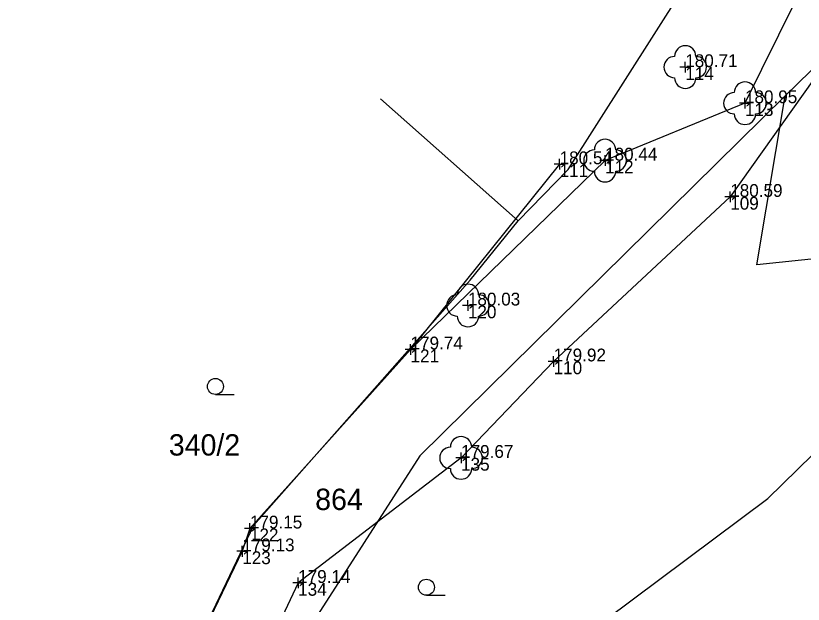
# Model space of a CAD drawing. Extents: x -744860 to -744734, y -966759 to -966608.
# Drawn here: x -744834.98 to -744798.06, y -966721.14 to -966693.56 of the extents above; entities that cross this region are included whole.
import ezdxf

# ---------------------------------------------------------------- set-up
doc = ezdxf.new("R2010")
doc.units = 0
for name, color, linetype in [('Bod polohopisu - výška', 7, 'Continuous'), ('Bod polohopisu - značka', 7, 'Continuous'), ('Bod polohopisu - číslo', 7, 'Continuous'), ('KM', 7, 'Continuous'), ('Ploty_opěrné zdi', 7, 'Continuous'), ('Stromy_porost', 7, 'Continuous'), ('Vstup na pozemek', 7, 'Continuous')]:
    doc.layers.add(name, color=color, linetype=linetype)

msp = doc.modelspace()

# ---------------------------------------------------------------- linework, layer by layer
at = {"layer": 'Bod polohopisu - značka'}
for p, q in [((-744803.59, -966695.97), (-744803.84, -966695.97)), ((-744803.59, -966695.97), (-744803.59, -966695.72)), ((-744803.59, -966695.97), (-744803.34, -966695.97)), ((-744803.59, -966695.97), (-744803.59, -966696.22)), ((-744800.79, -966697.66), (-744800.79, -966697.41)), ((-744800.79, -966697.66), (-744801.04, -966697.66)), ((-744800.79, -966697.66), (-744800.54, -966697.66)), ((-744800.79, -966697.66), (-744800.79, -966697.91)), ((-744807.35, -966700.35), (-744807.35, -966700.1)), ((-744809.48, -966700.52), (-744809.48, -966700.27)), ((-744807.35, -966700.35), (-744807.6, -966700.35)), ((-744807.35, -966700.35), (-744807.1, -966700.35)), ((-744807.35, -966700.35), (-744807.35, -966700.6)), ((-744809.48, -966700.52), (-744809.73, -966700.52)), ((-744809.48, -966700.52), (-744809.23, -966700.52)), ((-744809.48, -966700.52), (-744809.48, -966700.77)), ((-744801.48, -966702.05), (-744801.48, -966701.8)), ((-744801.48, -966702.05), (-744801.73, -966702.05)), ((-744801.48, -966702.05), (-744801.23, -966702.05)), ((-744801.48, -966702.05), (-744801.48, -966702.3)), ((-744813.78, -966707.14), (-744813.78, -966706.89)), ((-744813.78, -966707.14), (-744814.03, -966707.14)), ((-744813.78, -966707.14), (-744813.53, -966707.14)), ((-744813.78, -966707.14), (-744813.78, -966707.39)), ((-744816.47, -966709.2), (-744816.47, -966708.95)), ((-744816.47, -966709.2), (-744816.72, -966709.2)), ((-744816.47, -966709.2), (-744816.22, -966709.2)), ((-744816.47, -966709.2), (-744816.47, -966709.45)), ((-744809.76, -966709.76), (-744809.76, -966709.51)), ((-744809.76, -966709.76), (-744810.01, -966709.76)), ((-744809.76, -966709.76), (-744809.51, -966709.76)), ((-744809.76, -966709.76), (-744809.76, -966710.01)), ((-744814.1, -966714.28), (-744814.1, -966714.03)), ((-744814.1, -966714.28), (-744814.35, -966714.28)), ((-744814.1, -966714.28), (-744813.85, -966714.28)), ((-744814.1, -966714.28), (-744814.1, -966714.53)), ((-744824, -966717.59), (-744824, -966717.34)), ((-744824, -966717.59), (-744824.25, -966717.59)), ((-744824, -966717.59), (-744823.75, -966717.59)), ((-744824, -966717.59), (-744824, -966717.84)), ((-744824.36, -966718.66), (-744824.36, -966718.41)), ((-744824.36, -966718.66), (-744824.61, -966718.66)), ((-744824.36, -966718.66), (-744824.11, -966718.66)), ((-744824.36, -966718.66), (-744824.36, -966718.91)), ((-744821.74, -966720.14), (-744821.74, -966719.89)), ((-744821.74, -966720.14), (-744821.99, -966720.14)), ((-744821.74, -966720.14), (-744821.49, -966720.14)), ((-744821.74, -966720.14), (-744821.74, -966720.39))]:
    msp.add_line(p, q, dxfattribs=at)
at = {"layer": 'KM'}
for p, q in [((-744811.42, -966703.17), (-744817.88, -966697.46)), ((-744825.617, -966711.31), (-744824.742, -966711.31)), ((-744815.726, -966720.72), (-744814.851, -966720.72))]:
    msp.add_line(p, q, dxfattribs=at)
for points in [[(-744785.56, -966685.37), (-744792.95, -966691.5), (-744798.91, -966697.31)], [(-744811.42, -966703.17), (-744809.08, -966700.77), (-744801.02, -966688.1)], [(-744798.91, -966697.31), (-744816.04, -966714.19), (-744827.57, -966732.14), (-744834.06, -966749.64)], [(-744789.3, -966704.1), (-744800.23, -966705.23), (-744798.91, -966697.31)], [(-744829.77, -966729.91), (-744823.82, -966717.44), (-744813.68, -966705.96), (-744811.42, -966703.17)], [(-744822.22, -966737.39), (-744816.2, -966728.5), (-744799.72, -966716.19), (-744792.72, -966709.35), (-744789.3, -966704.1)]]:
    msp.add_lwpolyline(points, dxfattribs=at)
for centre in [(-744825.617, -966710.935), (-744815.726, -966720.345)]:
    msp.add_circle(centre, 0.375, dxfattribs=at)
at = {"layer": 'Ploty_opěrné zdi'}
for points in [[(-744809.48, -966700.52), (-744816.47, -966709.2), (-744824, -966717.59)], [(-744824.36, -966718.66), (-744829.77, -966729.91), (-744831.11, -966733.51)]]:
    msp.add_lwpolyline(points, dxfattribs=at)
at = {"layer": 'Stromy_porost'}
for points in [[(-744763.59, -966679.55), (-744765.78, -966677.46), (-744775.41, -966681.19), (-744781.69, -966681.97), (-744785.45, -966684.05), (-744788.92, -966688.06), (-744792.9, -966691.9), (-744797.56, -966696.54), (-744801.48, -966702.05), (-744809.76, -966709.76), (-744814.1, -966714.28), (-744821.74, -966720.14), (-744827.24, -966731.82), (-744829.32, -966738.32), (-744831.32, -966741.72), (-744834.98, -966747.08), (-744831.81, -966750.81), (-744822.41, -966749.82)], [(-744781.18, -966678.65), (-744792.93, -966685.32), (-744796.85, -966689.7), (-744800.79, -966697.66), (-744807.35, -966700.35), (-744816.47, -966709.2)]]:
    msp.add_lwpolyline(points, dxfattribs=at)
for centre in [(-744803.59, -966695.97), (-744800.79, -966697.66), (-744807.35, -966700.35), (-744813.78, -966707.14), (-744814.1, -966714.28)]:
    msp.add_circle(centre, 0.0005, dxfattribs=at)
for centre, start, end in [((-744803.59, -966695.47), 0, 180), ((-744804.09, -966695.97), 90, 270), ((-744803.09, -966695.97), 270, 90), ((-744803.59, -966696.47), 180, 360), ((-744800.79, -966697.16), 0, 180), ((-744801.29, -966697.66), 90, 270), ((-744800.29, -966697.66), 270, 90), ((-744800.79, -966698.16), 180, 360), ((-744807.35, -966699.85), 0, 180), ((-744807.85, -966700.35), 90, 270), ((-744806.85, -966700.35), 270, 90), ((-744807.35, -966700.85), 180, 360), ((-744813.78, -966706.64), 0, 180), ((-744814.28, -966707.14), 90, 270), ((-744813.28, -966707.14), 270, 90), ((-744813.78, -966707.64), 180, 360), ((-744814.1, -966713.78), 0, 180), ((-744814.6, -966714.28), 90, 270), ((-744813.6, -966714.28), 270, 90), ((-744814.1, -966714.78), 180, 360)]:
    msp.add_arc(centre, 0.5, start, end, dxfattribs=at)
at = {"layer": 'Vstup na pozemek'}
msp.add_lwpolyline([(-744824, -966717.59), (-744824.36, -966718.66)], dxfattribs=at)

# ---------------------------------------------------------------- texts
at = {"layer": 'Bod polohopisu - výška'}
for s, p in [('180.71', (-744803.59, -966695.97)), ('180.95', (-744800.79, -966697.66)), ('180.44', (-744807.35, -966700.35)), ('180.54', (-744809.48, -966700.52)), ('180.59', (-744801.48, -966702.05)), ('180.03', (-744813.78, -966707.14)), ('179.74', (-744816.47, -966709.2)), ('179.92', (-744809.76, -966709.76)), ('179.67', (-744814.1, -966714.28)), ('179.15', (-744824, -966717.59)), ('179.13', (-744824.36, -966718.66)), ('179.14', (-744821.74, -966720.14))]:
    msp.add_text(s, height=0.6, dxfattribs=at).set_placement(p)
at = {"layer": 'Bod polohopisu - číslo'}
for s, p in [('114', (-744803.59, -966696.57)), ('113', (-744800.79, -966698.26)), ('112', (-744807.35, -966700.95)), ('111', (-744809.48, -966701.12)), ('109', (-744801.48, -966702.65)), ('120', (-744813.78, -966707.74)), ('121', (-744816.47, -966709.8)), ('110', (-744809.76, -966710.36)), ('135', (-744814.1, -966714.88)), ('122', (-744824, -966718.19)), ('123', (-744824.36, -966719.26)), ('134', (-744821.74, -966720.74))]:
    msp.add_text(s, height=0.6, dxfattribs=at).set_placement(p)
at = {"layer": 'KM'}
for s, p in [('340/2', (-744827.802, -966714.172)), ('864', (-744820.94, -966716.724))]:
    msp.add_text(s, height=1, dxfattribs=at).set_placement(p)

doc.saveas('drawing.dxf')
